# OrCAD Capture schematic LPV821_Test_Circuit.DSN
size A; title: LPV821, 650nA, Precision, Nanopower, Zero-Drift Amplifier; rev: 1.2; note: Datasheet: SNOSD36A   EVM: N/A
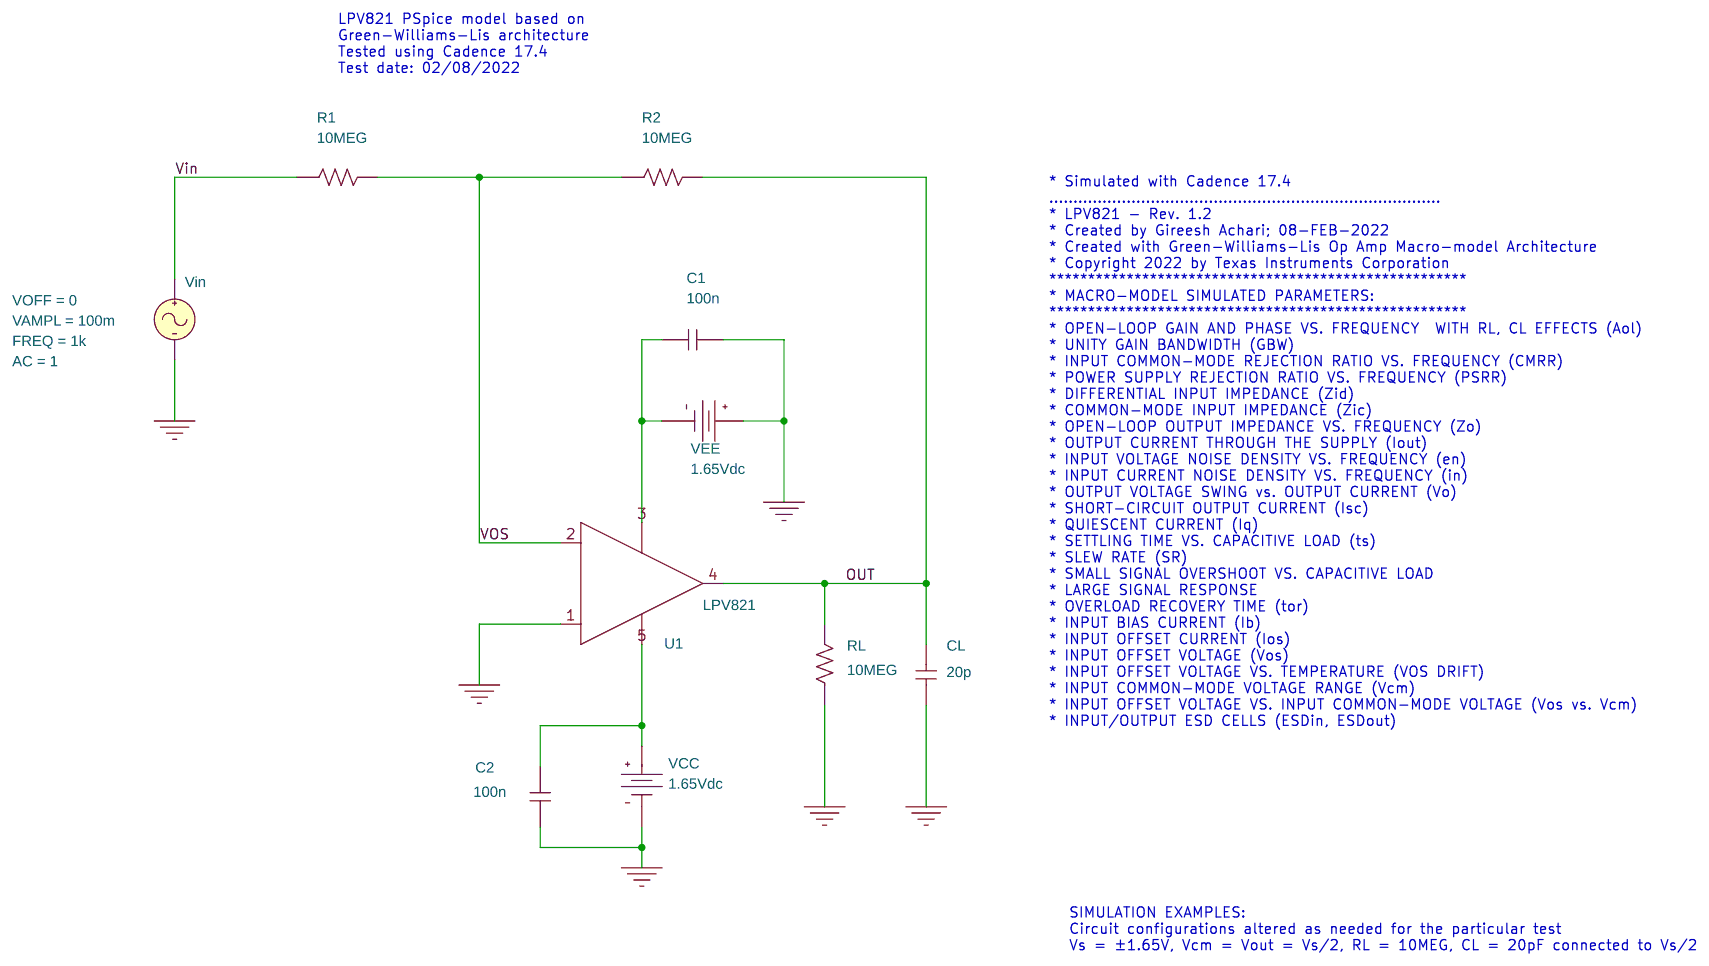
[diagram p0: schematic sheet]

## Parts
C1  100n  [cap196]
C2  100n  [cap196]
CL  20p  [cap196]
R1  10MEG  [AXRC05]
R2  10MEG  [AXRC05]
RL  10MEG  [AXRC05]
U1  LPV821
VCC  VDC
VEE  VDC
Vin  VSIN

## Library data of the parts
C1 C2 CL = C
R1 R2 RL = R
U1 = LPV821
VCC VEE = VDC: DC: 1.65Vdc
Vin = VSIN: AC: 1; FREQ: 1k; VAMPL: 100m; VOFF: 0

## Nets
Vin: R1.1 Vin.1(+)
0: C1.2 C2.1 CL.2 RL.1 U1.1(+) VCC.1(-) VEE.0(+) Vin.2(-)
OUT: CL.1 R2.2 RL.2 U1.4(OUT)
VOS: R1.2 R2.1 U1.2(-)
N27303: C1.1 U1.3(V-) VEE.1(-)
N27354: C2.2 U1.5(V+) VCC.0(+)

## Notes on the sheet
- LPV821 PSpice model based on
  Green-Williams-Lis architecture
  Tested using Cadence 17.4
  Test date: 02/08/2022
- * Simulated with Cadence 17.4
  .................................................................................
  * LPV821 - Rev. 1.2
  * Created by Gireesh Achari; 08-FEB-2022
  * Created with Green-Williams-Lis Op Amp Macro-model Architecture
  * Copyright 2022 by Texas Instruments Corporation
  ******************************************************
  * MACRO-MODEL SIMULATED PARAMETERS:
  ******************************************************
  * OPEN-LOOP GAIN AND PHASE VS. FREQUENCY  WITH RL, CL EFFECTS (Aol)
  * UNITY GAIN BANDWIDTH (GBW)
  * INPUT COMMON-MODE REJECTION RATIO VS. FREQUENCY (CMRR)
  * POWER SUPPLY REJECTION RATIO VS. FREQUENCY (PSRR)
  * DIFFERENTIAL INPUT IMPEDANCE (Zid)
  * COMMON-MODE INPUT IMPEDANCE (Zic)
  * OPEN-LOOP OUTPUT IMPEDANCE VS. FREQUENCY (Zo)
  * OUTPUT CURRENT THROUGH THE SUPPLY (Iout)
  * INPUT VOLTAGE NOISE DENSITY VS. FREQUENCY (en)
  * INPUT CURRENT NOISE DENSITY VS. FREQUENCY (in)
  * OUTPUT VOLTAGE SWING vs. OUTPUT CURRENT (Vo)
  * SHORT-CIRCUIT OUTPUT CURRENT (Isc)
  * QUIESCENT CURRENT (Iq)
  * SETTLING TIME VS. CAPACITIVE LOAD (ts)
  * SLEW RATE (SR)
  * SMALL SIGNAL OVERSHOOT VS. CAPACITIVE LOAD
  * LARGE SIGNAL RESPONSE
  * OVERLOAD RECOVERY TIME (tor)
  * INPUT BIAS CURRENT (Ib)
  * INPUT OFFSET CURRENT (Ios)
  * INPUT OFFSET VOLTAGE (Vos)
  * INPUT OFFSET VOLTAGE VS. TEMPERATURE (VOS DRIFT)
  * INPUT COMMON-MODE VOLTAGE RANGE (Vcm)
  * INPUT OFFSET VOLTAGE VS. INPUT COMMON-MODE VOLTAGE (Vos vs. Vcm)
  * INPUT/OUTPUT ESD CELLS (ESDin, ESDout)
- SIMULATION EXAMPLES:
  Circuit configurations altered as needed for the particular test
  Vs = ±1.65V, Vcm = Vout = Vs/2, RL = 10MEG, CL = 20pF connected to Vs/2
